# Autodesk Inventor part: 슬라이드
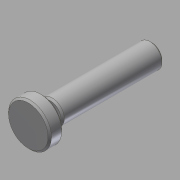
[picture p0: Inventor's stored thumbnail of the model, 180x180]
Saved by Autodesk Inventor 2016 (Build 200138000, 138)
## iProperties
Created: 2015-09
Part Number: 슬라이드
Material: 강철, 연강
Document SubType Name: Modeling
Designer: mduedu
Density: 1 g/cm^3
Appearance: 강철
Author: mduedu
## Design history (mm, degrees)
sketch "스케치1"
  geometry: C1 r 12.5 at (0, 0); 1 further point
  constraints: 1 centre point, 1 coincident
  dimensions: "d0" = 25 diameter of C1
extrude "돌출1" new body sketch "스케치1" distance "d1" = 8; taper "d2" = 0 deg
sketch "스케치2"
  geometry: C1 r 4 at (0, 0); 1 further point
  constraints: 1 centre point, 1 coincident
  dimensions: "d3" = 8 diameter of C1
extrude "돌출2" join sketch "스케치2" distance "d4" = 5; taper "d5" = 0 deg
sketch "스케치3"
  geometry: C1 r 7 at (0, 0); 1 further point
  constraints: 1 centre point, 1 coincident
  dimensions: "d6" = 14 diameter of C1
extrude "돌출3" join sketch "스케치3" distance "d7" = 59; taper "d8" = 0 deg
hole "구멍1" diameter "d11" = 4.134; stored, may be unused: countersink angle "d15" = 90 deg, drill point angle "d17" = 118 deg; dims "d9" = 10, "d10" = 10, "d12" = 9, "d13" = 4, "d14" = 2, "d16" = 12
chamfer "모따기1" distance "d18" = 1; stored, may be unused: second distance "d19" = 2, angle "d20" = 45 deg
node "솔리드1"
